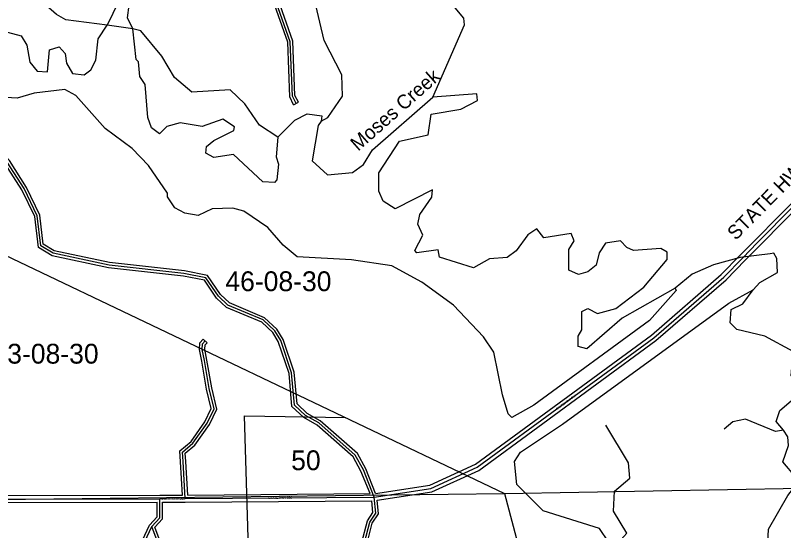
# Model space of a CAD drawing. Extents: x 418523 to 616617, y 1878279 to 2196743.
# Drawn here: x 564663 to 573384, y 1971295 to 1977147 of the extents above; entities that cross this region are included whole.
import ezdxf

# ---------------------------------------------------------------- set-up
doc = ezdxf.new("R2010")
doc.units = 0
for name, color, linetype in [('Level 1', 7, 'Continuous'), ('Level 2', 7, 'Continuous'), ('Level 22', 7, 'Continuous'), ('Level 23', 7, 'Continuous'), ('Level 28', 7, 'Continuous'), ('Level 31', 7, 'Continuous'), ('Level 32', 7, 'Continuous'), ('Level 34', 7, 'Continuous'), ('Level 41', 7, 'Continuous'), ('Level 5', 7, 'Continuous'), ('Level 7', 7, 'Continuous')]:
    doc.layers.add(name, color=color, linetype=linetype)

msp = doc.modelspace()

# ---------------------------------------------------------------- linework, layer by layer
at = {"layer": 'Level 1'}
for p, q in [((563450.632, 1974946.842), (570215.137, 1971717.725)), ((567356.046, 1969642.211), (567262.093, 1972599.901)), ((567262.093, 1972599.901), (568413.529, 1972577.743)), ((570215.137, 1971717.725), (576907.534, 1971833.943)), ((563291.494, 1971636.047), (570215.137, 1971717.725)), ((570215.137, 1971717.725), (570759.854, 1969688.182))]:
    msp.add_line(p, q, dxfattribs=at)
at = {"layer": 'Level 22'}
for p, q in [((572920.444, 1974393.845), (573085.501, 1974561.481)), ((568737.065, 1971675.057), (569379.242, 1971773.542)), ((566591.6, 1971658.396), (568737.065, 1971675.057)), ((564535.644, 1971652.911), (566302.831, 1971656.555)), ((566302.831, 1971656.555), (566591.6, 1971658.396))]:
    msp.add_line(p, q, dxfattribs=at)
for points in [[(573085.501, 1974561.481), (573915.845, 1975404.017), (574244.112, 1975774.574)], [(569379.242, 1971773.542), (569905.29, 1972013.771), (571909.987, 1973483.739), (572703.548, 1974173.599), (572920.444, 1974393.845)]]:
    msp.add_lwpolyline(points, dxfattribs=at)
at = {"layer": 'Level 23'}
for p, q in [((572891.941, 1974421.91), (573056.999, 1974589.545)), ((572948.948, 1974365.78), (573114.004, 1974533.415)), ((568752.209, 1971717.847), (569367.684, 1971812.237)), ((564561.135, 1971692.964), (566302.749, 1971696.555)), ((566302.576, 1971696.555), (566559.303, 1971698.191)), ((566619.375, 1971698.613), (568688.82, 1971714.684)), ((568770.347, 1971639.691), (569390.802, 1971734.846)), ((564536.166, 1971612.911), (566272.734, 1971616.491)), ((566332.736, 1971616.742), (566591.856, 1971618.396)), ((566591.912, 1971618.396), (568710.539, 1971634.848))]:
    msp.add_line(p, q, dxfattribs=at)
for points in [[(573057.011, 1974589.558), (573886.608, 1975431.338), (574214.17, 1975801.098)], [(573113.991, 1974533.402), (573945.082, 1975376.696), (574274.054, 1975748.05)], [(569367.684, 1971812.237), (569884.944, 1972048.453), (571884.995, 1973515.016), (572676.134, 1974202.771), (572891.943, 1974421.913)], [(569390.802, 1971734.846), (569925.638, 1971979.087), (571934.979, 1973452.462), (572730.962, 1974144.426), (572948.945, 1974365.777)]]:
    msp.add_lwpolyline(points, dxfattribs=at)
at = {"layer": 'Level 31'}
for points in [[(567848.799, 1976145.749), (567807.434, 1976229.126), (567784.167, 1976846.301), (567378.603, 1977997.88), (567329.154, 1978147.824), (567096.413, 1978465.493), (567022.385, 1978815.508), (566864.759, 1979099.541), (566557.257, 1979458.852), (566324.064, 1979584.518), (566008.159, 1979876.942), (565566.997, 1980061.672), (565492.159, 1980203.681), (565284.344, 1980454.39), (565243.608, 1980787.961), (565210.441, 1980846.229), (565202.687, 1981046.257), (565044.94, 1981271.751), (565046.426, 1981872.141), (564730.718, 1982231.488), (564706.008, 1982373.012)], [(568737.065, 1971675.057), (568613.09, 1971983.729), (568521.781, 1972150.863), (568106.02, 1972518.782), (567956.129, 1972602.417), (567831.387, 1972719.449), (567798.949, 1973086.452), (567674.809, 1973453.678), (567608.436, 1973562.206), (567475.469, 1973687.623), (567075.751, 1973855.506), (566967.793, 1973955.771), (566826.464, 1974164.487), (566576.553, 1974215.28), (565726.415, 1974309.001), (565093.417, 1974444.386), (564951.79, 1974528.013), (564911.07, 1974869.949), (564761.755, 1975178.698), (564570.858, 1975479.188), (564097.168, 1975997.486)], [(566591.6, 1971658.396), (566567.869, 1972078.11), (566559.248, 1972186.864), (566679.119, 1972286.576), (566840.238, 1972515.65), (566919.005, 1972676.921), (566863.719, 1972908.701), (566808.324, 1973225.942), (566784.832, 1973352.186), (566787.844, 1973416.91), (566817.115, 1973449.205)], [(569521.172, 1969648.749), (569474.434, 1969880.869), (569316.651, 1970123.071), (569225.138, 1970206.562), (569176.398, 1970665.243), (569101.742, 1970898.885), (569002.099, 1971032.581), (568685.327, 1970999.876), (568618.747, 1971025.127), (568627.315, 1971158.567), (568686.256, 1971391.892), (568753.449, 1971491.737), (568737.065, 1971675.057)], [(566210.352, 1971340.039), (566302.303, 1971439.819), (566302.831, 1971656.555)], [(565874.59, 1969219.983), (565765.254, 1970090.891), (565782.573, 1970424.318), (566210.352, 1971340.039)], [(566441.659, 1970547.438), (566375.649, 1970806.156), (566350.64, 1970831.31), (566334.586, 1971014.63), (566210.352, 1971340.039)]]:
    msp.add_lwpolyline(points, dxfattribs=at)
at = {"layer": 'Level 32'}
for p, q in [((567821.924, 1976132.416), (567875.674, 1976159.082)), ((566794.886, 1973469.352), (566839.344, 1973429.056))]:
    msp.add_line(p, q, dxfattribs=at)
for points in [[(567821.924, 1976132.416), (567777.697, 1976221.561), (567754.359, 1976840.626), (567350.206, 1977988.198), (567302.148, 1978133.921), (567068.398, 1978452.97), (566993.966, 1978804.891), (566839.997, 1979082.336), (566538.101, 1979435.096), (566306.479, 1979559.916), (565991.674, 1979851.32), (565545.477, 1980038.159), (565467.072, 1980186.937), (565255.631, 1980442.019), (565214.559, 1980778.351), (565180.746, 1980837.751), (565173.05, 1981036.285), (565014.917, 1981262.332), (565016.398, 1981860.866), (564702.614, 1982218.021), (564677.697, 1982360.735)], [(567875.674, 1976159.082), (567837.171, 1976236.691), (567813.974, 1976851.977), (567407, 1978007.561), (567356.159, 1978161.726), (567124.429, 1978478.016), (567050.804, 1978826.126), (566889.522, 1979116.747), (566576.413, 1979482.609), (566341.649, 1979609.121), (566024.643, 1979902.565), (565588.517, 1980085.186), (565517.245, 1980220.426), (565313.057, 1980466.761), (565272.658, 1980797.571), (565240.136, 1980854.706), (565232.323, 1981056.23), (565074.964, 1981281.168), (565076.455, 1981883.416), (564758.82, 1982244.955), (564734.318, 1982385.29)], [(568688.82, 1971714.684), (568585.912, 1971970.901), (568497.969, 1972131.874), (568088.569, 1972494.165), (567938.292, 1972578.016), (567802.511, 1972705.403), (567769.38, 1973080.241), (567647.464, 1973440.89), (567584.934, 1973543.133), (567458.839, 1973662.068), (567059.231, 1973829.905), (566944.87, 1973936.117), (566808.489, 1974137.526), (566571.913, 1974185.609), (565721.622, 1974279.346), (565082.367, 1974416.07), (564923.754, 1974509.726), (564881.874, 1974861.412), (564735.503, 1975164.076), (564546.942, 1975460.886), (564094.642, 1975955.78)], [(568752.209, 1971717.847), (568640.268, 1971996.556), (568545.594, 1972169.852), (568123.472, 1972543.4), (567973.967, 1972626.819), (567860.264, 1972733.495), (567828.518, 1973092.664), (567702.155, 1973466.466), (567631.938, 1973581.279), (567492.099, 1973713.178), (567092.271, 1973881.106), (566990.715, 1973975.426), (566844.439, 1974191.448), (566581.194, 1974244.951), (565731.208, 1974338.655), (565104.466, 1974472.701), (564979.825, 1974546.3), (564940.267, 1974878.486), (564788.009, 1975193.321), (564594.773, 1975497.491), (564127.704, 1976008.545)], [(566559.303, 1971698.191), (566537.935, 1972076.077), (566528.113, 1972199.988), (566656.872, 1972307.093), (566814.327, 1972530.959), (566887.328, 1972680.423), (566834.324, 1972902.636), (566778.799, 1973220.618), (566754.702, 1973350.113), (566758.376, 1973429.071), (566794.886, 1973469.352)], [(566619.375, 1971698.613), (566597.804, 1972080.141), (566590.383, 1972173.74), (566701.368, 1972266.059), (566866.149, 1972500.341), (566950.683, 1972673.418), (566893.114, 1972914.768), (566837.849, 1973231.267), (566814.962, 1973354.261), (566817.312, 1973404.748), (566839.344, 1973429.056)], [(566185.14, 1971356.949), (566272.331, 1971451.566), (566272.734, 1971616.491)], [(566245.009, 1971333.375), (566332.274, 1971428.072), (566332.735, 1971616.742)], [(569491.761, 1969642.826), (569446.158, 1969869.311), (569293.604, 1970103.488), (569196.509, 1970192.072), (569146.889, 1970659.028), (569074.691, 1970884.978), (568988.229, 1971000.988), (568681.335, 1970969.304), (568587.389, 1971004.935), (568597.553, 1971163.241), (568658.449, 1971404.306), (568722.62, 1971499.662), (568710.539, 1971634.848)], [(569547.099, 1969671.972), (569502.709, 1969892.427), (569339.699, 1970142.652), (569253.768, 1970221.052), (569205.907, 1970671.458), (569128.793, 1970912.792), (569015.969, 1971064.173), (568689.318, 1971030.449), (568650.106, 1971045.32), (568657.078, 1971153.892), (568714.064, 1971379.478), (568784.277, 1971483.812), (568770.348, 1971639.691)], [(565844.343, 1969220.064), (565735.155, 1970089.792), (565752.916, 1970431.716), (566185.139, 1971356.949)], [(566468.84, 1970562.253), (566402.695, 1970821.504), (566379.579, 1970844.755), (566364.108, 1971021.418), (566245.009, 1971333.375)]]:
    msp.add_lwpolyline(points, dxfattribs=at)
at = {"layer": 'Level 5'}
for points in [[(569401.82, 1976216.616), (569762.964, 1977040.74), (569754.852, 1977115.801), (569538.963, 1977374.915), (569497.639, 1977483.416), (569506.398, 1977616.8), (569615.128, 1977724.814)], [(565994.764, 1976994.579), (565936.801, 1977119.821), (565953.929, 1977261.475), (566079.827, 1977527.842), (566096.895, 1977644.486), (565963.244, 1977569.881), (565703.127, 1977037.206)], [(564344.194, 1977016.577), (564727.345, 1976915.301), (564793.709, 1976806.729), (564826.434, 1976614.895), (564909.467, 1976514.574), (565026.15, 1976505.875), (565051.976, 1976755.861), (565160.448, 1976788.883), (565226.901, 1976713.632), (565243.224, 1976605.19), (565309.517, 1976488.288), (565442.87, 1976471.19), (565518.061, 1976529.282), (565576.771, 1976637.456), (565602.567, 1976879.141), (565703.127, 1977037.206)], [(567641.386, 1975763.812), (567623.989, 1975538.757), (567648.741, 1975455.326), (567631.484, 1975280.331), (567606.374, 1975247.051), (567473.021, 1975255.809), (567140.548, 1975565.341), (566915.373, 1975532.748), (566823.829, 1975583.057), (566832.399, 1975658.05), (566915.989, 1975724.482), (567141.463, 1975840.438), (567149.932, 1975882.089), (567016.807, 1975965.909), (566783.133, 1975883.294), (566533.166, 1975925.791), (566382.984, 1975884.569), (566299.363, 1975801.506), (566207.859, 1975868.486), (566166.567, 1975985.328), (566134.429, 1976360.556), (566076.366, 1976452.457), (566060.213, 1976619.211), (566035.302, 1976644.321), (565994.764, 1976994.579)], [(568133.814, 1975945.603), (568100.304, 1975895.681), (568032.34, 1975495.771), (568206.887, 1975336.821), (568490.384, 1975360.915), (568615.754, 1975452.188), (568716.314, 1975618.594), (569401.82, 1976216.616)], [(572154.174, 1974048.584), (571552.876, 1973708.718), (571151.593, 1973359.905), (571051.65, 1973385.234), (571052.008, 1973501.946), (571093.918, 1973576.839), (571094.604, 1973785.253), (571161.395, 1973818.365), (571269.609, 1973759.656), (571478.183, 1973817.349), (571795.746, 1974058.059), (572063.547, 1974373.99), (572063.815, 1974457.361), (571988.913, 1974499.271), (571680.405, 1974475.277), (571605.474, 1974508.846), (571530.68, 1974584.137), (571363.887, 1974559.645), (571288.497, 1974451.541), (571254.699, 1974309.917), (571162.768, 1974235.185), (571054.265, 1974202.202), (570946.052, 1974252.542), (570946.808, 1974485.957), (571005.488, 1974585.831), (570972.435, 1974669.292), (570663.829, 1974620.256), (570580.785, 1974720.588), (570480.524, 1974654.225), (570346.554, 1974471.249), (570246.253, 1974396.546), (570046.148, 1974380.533), (569862.425, 1974281.078), (569479.314, 1974399.036), (569462.933, 1974482.427), (569221.047, 1974449.874), (569196.136, 1974474.974), (569288.395, 1974649.749), (569230.462, 1974774.951), (569255.8, 1974883.264), (569389.83, 1975082.911), (569398.429, 1975166.242), (568972.592, 1974950.871), (568839.468, 1975034.652), (568789.844, 1975151.524), (568790.49, 1975359.939), (569025.089, 1975717.65), (569350.436, 1975791.626), (569384.533, 1976024.911), (569718.18, 1976082.187), (569910.243, 1976181.612), (569902.131, 1976256.664), (569401.82, 1976216.616)], [(567641.386, 1975763.812), (567833.737, 1975954.92), (567975.719, 1976029.493), (568142.344, 1976003.925), (568133.814, 1975945.603)], [(573230.834, 1974436.896), (572888.916, 1974396.321), (572588.55, 1974313.936), (572346.436, 1974206.35), (572154.174, 1974048.584)], [(573037.796, 1974029.035), (573113.086, 1974112.168), (573313.519, 1974228.223), (573305.706, 1974386.646), (573272.554, 1974445.097), (573230.834, 1974436.896)], [(573559.269, 1972876.946), (573567.868, 1972960.278), (573468.124, 1973052.308), (573494.009, 1973327.305), (573169.479, 1973503.415), (572852.929, 1973579.492), (572778.157, 1973654.743), (572786.954, 1973804.766), (572920.566, 1973871.03), (573037.796, 1974029.035)], [(573382.763, 1972435.683), (573299.729, 1972535.975), (573341.798, 1972660.888), (573550.799, 1972835.265), (573559.269, 1972876.946)], [(573382.763, 1972435.683), (573291.001, 1972419.301), (572949.67, 1972562.131), (572807.848, 1972529.238), (572707.557, 1972446.205)], [(573203.562, 1971152.431), (573019.699, 1971011.336), (573044.323, 1970894.534), (573226.832, 1970618.84), (573217.845, 1970418.806), (573142.594, 1970344.002), (572967.63, 1970369.601), (572826.294, 1970495.101), (572510.66, 1970854.586), (572452.369, 1970871.456), (572277.075, 1970805.321), (572093.91, 1970872.601), (571893.448, 1970748.205), (571743.384, 1970748.693), (571668.591, 1970823.954), (571652.179, 1970907.376), (571510.913, 1971049.556), (571536.411, 1971191.171), (571603.331, 1971266.003), (571454.093, 1971516.586), (571463.149, 1971741.631), (571638.701, 1971891.097), (571622.588, 1972066.231), (571365.534, 1972492.237)], [(573203.562, 1971152.431), (573212.419, 1971310.826), (573430.398, 1971693.577), (573522.458, 1971809.991), (573522.756, 1971901.693), (573373.289, 1972077.245), (573440.568, 1972260.42), (573432.555, 1972360.492), (573382.763, 1972435.683)]]:
    msp.add_lwpolyline(points, dxfattribs=at)
at = {"layer": 'Level 7'}
msp.add_line((565994.764, 1976994.579), (565703.127, 1977037.206), dxfattribs=at)
for points in [[(568133.814, 1975945.603), (568208.975, 1975987.056), (568376.485, 1976228.253), (568368.93, 1976470.048), (568170.129, 1976862.505), (568054.988, 1977346.374), (567856.354, 1977788.851), (567566.109, 1978264.979), (567508.931, 1978631.966), (567475.819, 1978698.757), (567468.235, 1978932.213), (567443.254, 1978948.953), (567412.519, 1979757.671), (567222.973, 1980433.534), (567198.032, 1980450.304), (567207.148, 1980692.03), (567491.758, 1981057.911), (567618.342, 1981532.664), (567603.432, 1982074.586), (567537.616, 1982349.922)], [(565703.127, 1977037.206), (565236.484, 1977097.071), (565128.271, 1977155.781), (564421.673, 1977774.956)], [(567641.386, 1975763.812), (567433.399, 1975897.843), (567267.45, 1976140.156), (567101.254, 1976299.068), (566667.694, 1976275.461), (566468.145, 1976442.842), (566327.208, 1976685.056), (566086.367, 1976969.28), (565994.764, 1976994.579)], [(572154.174, 1974048.584), (572162.445, 1974023.543), (571861.224, 1973682.731), (570549.32, 1972719.932), (570298.766, 1972579.026), (570257.214, 1972620.846), (570191.209, 1972837.82), (570092.739, 1973321.65), (569976.592, 1973497.072), (569635.978, 1973856.646), (569278.324, 1974116.216), (568937.153, 1974300.726), (568478.851, 1974368.921), (567862.095, 1974404.265), (567704.119, 1974538.136), (567529.711, 1974738.798), (567255.202, 1974923.078), (567130.258, 1974956.817), (566896.803, 1974949.234), (566738.18, 1974874.731), (566588.196, 1974900.229), (566471.682, 1974958.939), (566388.738, 1975084.281), (566388.867, 1975125.961), (566173.136, 1975443.426), (565990.359, 1975635.758), (565682.627, 1975861.849), (565350.413, 1976238.063), (565225.569, 1976305.143), (564875.31, 1976264.607), (564683.377, 1976206.873), (564483.342, 1976215.831)], [(571989.513, 1969203.516), (572030.954, 1969447.277), (571998.061, 1969589.09), (572057.556, 1969939.059), (572058.282, 1970164.104), (571992.108, 1970322.726), (571892.493, 1970456.428), (571476.498, 1970716.199), (571401.824, 1970824.83), (571394.598, 1971166.628), (571295.053, 1971317), (570653.804, 1971519.166), (570354.641, 1971820.229), (570330.486, 1972078.754), (570397.536, 1972186.898), (570873.722, 1972502.141), (572762.202, 1973879.898), (573037.796, 1974029.035)]]:
    msp.add_lwpolyline(points, dxfattribs=at)

# ---------------------------------------------------------------- texts
at = {"layer": 'Level 2'}
for s, p in [('46-08-30', (567046.879, 1974014.591)), ('33-08-30', (564403.322, 1973191.502)), ('50', (567793.689, 1971981.245))]:
    msp.add_text(s, height=225, dxfattribs=at).set_placement(p)
at = {"layer": 'Level 28'}
msp.add_text('STATE HWY 206', height=160, rotation=45.4167361, dxfattribs=at).set_placement((572841.386, 1974584.066))
at = {"layer": 'Level 34'}
for height, rotation, p in [(25, 36.2503611, (570811.399, 1972662.688)), (25, 0.3646305, (566318.793, 1971644.159)), (24.99916, 0.4441472, (567535.94, 1971653.231))]:
    msp.add_text('STATE HWY 206', height=height, rotation=rotation, dxfattribs=at).set_placement(p)
at = {"layer": 'Level 41'}
msp.add_text('Moses Creek', height=160, rotation=41.4772778, dxfattribs=at).set_placement((568553.383, 1975597.952))

doc.saveas('drawing.dxf')
